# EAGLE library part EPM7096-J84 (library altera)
EPM7096 MAX 7000 family
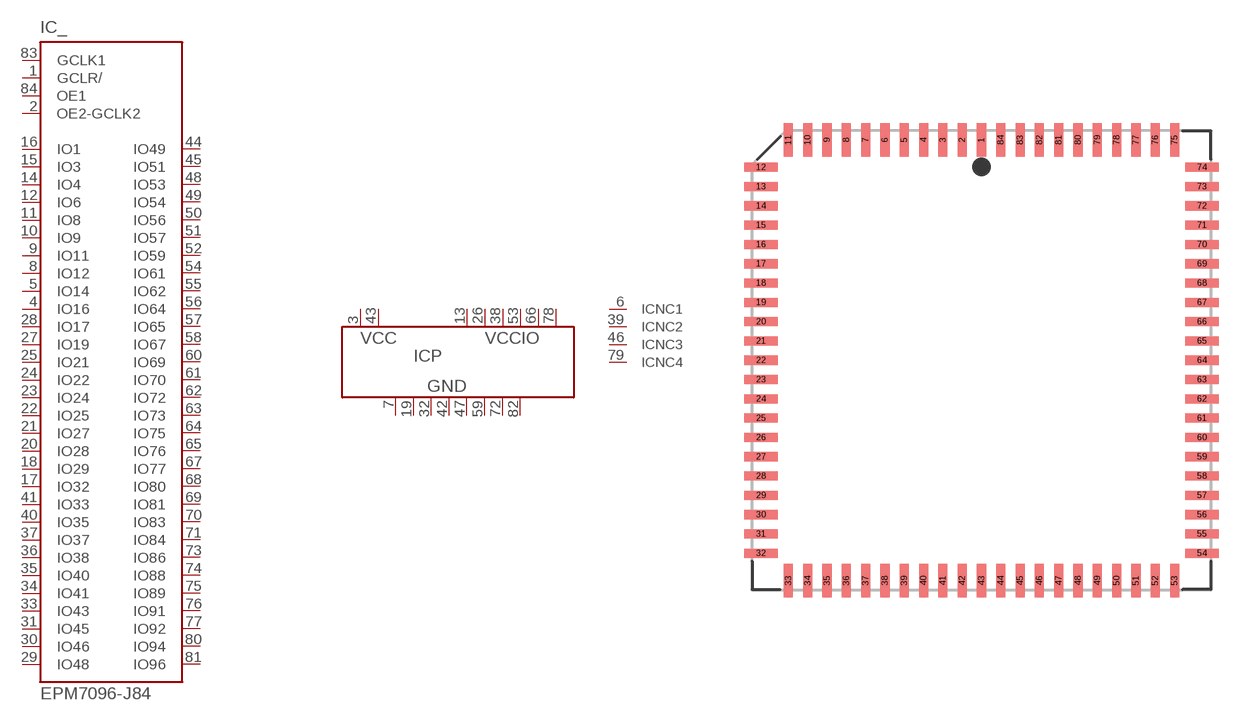
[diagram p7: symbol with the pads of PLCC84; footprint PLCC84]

Designator prefix IC; gates _=7096-84 P=PWR8-2-6 NC1=NC NC2=NC NC3=NC NC4=NC

## EPM7096-J84 (MPN: EPM7096LC84-10; OC_FARNELL: unknown; OC_NEWARK: 51R9659)  [PLCC84]
1  _:GCLR/  in
2  _:OE2-GCLK2  in
3  P:VCC  pwr
4  _:IO16
5  _:IO14
6  NC1:NC  nc
7  P:GND  pwr
8  _:IO12
9  _:IO11
10  _:IO9
11  _:IO8
12  _:IO6
13  P:VCCIO  pwr
14  _:IO4
15  _:IO3
16  _:IO1
17  _:IO32
18  _:IO29
19  P:GND  pwr
20  _:IO28
21  _:IO27
22  _:IO25
23  _:IO24
24  _:IO22
25  _:IO21
26  P:VCCIO  pwr
27  _:IO19
28  _:IO17
29  _:IO48
30  _:IO46
31  _:IO45
32  P:GND  pwr
33  _:IO43
34  _:IO41
35  _:IO40
36  _:IO38
37  _:IO37
38  P:VCCIO  pwr
39  NC2:NC  nc
40  _:IO35
41  _:IO33
42  P:GND  pwr
43  P:VCC  pwr
44  _:IO49
45  _:IO51
46  NC3:NC  nc
47  P:GND  pwr
48  _:IO53
49  _:IO54
50  _:IO56
51  _:IO57
52  _:IO59
53  P:VCCIO  pwr
54  _:IO61
55  _:IO62
56  _:IO64
57  _:IO65
58  _:IO67
59  P:GND  pwr
60  _:IO69
61  _:IO70
62  _:IO72
63  _:IO73
64  _:IO75
65  _:IO76
66  P:VCCIO  pwr
67  _:IO77
68  _:IO80
69  _:IO81
70  _:IO83
71  _:IO84
72  P:GND  pwr
73  _:IO86
74  _:IO88
75  _:IO89
76  _:IO91
77  _:IO92
78  P:VCCIO  pwr
79  NC4:NC  nc
80  _:IO94
81  _:IO96
82  P:GND  pwr
83  _:GCLK1  in
84  _:OE1  in

## Footprint PLCC84 (pad centres in mm)
Plastic J-Lead Chip Carrier
smd 0.6 x 2.2: 1 0,14.5; 2 -1.27,14.5; 3 -2.54,14.5; 4 -3.81,14.5; 5 -5.08,14.5; 6 -6.35,14.5; 7 -7.62,14.5; 8 -8.89,14.5; 9 -10.16,14.5; 10 -11.43,14.5; 11 -12.7,14.5; 33 -12.7,-14.5; 34 -11.43,-14.5; 35 -10.16,-14.5; 36 -8.89,-14.5; 37 -7.62,-14.5; 38 -6.35,-14.5; 39 -5.08,-14.5; 40 -3.81,-14.5; 41 -2.54,-14.5; 42 -1.27,-14.5; 43 0,-14.5; 44 1.27,-14.5; 45 2.54,-14.5; 46 3.81,-14.5; 47 5.08,-14.5; 48 6.35,-14.5; 49 7.62,-14.5; 50 8.89,-14.5; 51 10.16,-14.5; 52 11.43,-14.5; 53 12.7,-14.5; 75 12.7,14.5; 76 11.43,14.5; 77 10.16,14.5; 78 8.89,14.5; 79 7.62,14.5; 80 6.35,14.5; 81 5.08,14.5; 82 3.81,14.5; 83 2.54,14.5; 84 1.27,14.5
smd 2.2 x 0.6: 12 -14.5,12.7; 13 -14.5,11.43; 14 -14.5,10.16; 15 -14.5,8.89; 16 -14.5,7.62; 17 -14.5,6.35; 18 -14.5,5.08; 19 -14.5,3.81; 20 -14.5,2.54; 21 -14.5,1.27; 22 -14.5,0; 23 -14.5,-1.27; 24 -14.5,-2.54; 25 -14.5,-3.81; 26 -14.5,-5.08; 27 -14.5,-6.35; 28 -14.5,-7.62; 29 -14.5,-8.89; 30 -14.5,-10.16; 31 -14.5,-11.43; 32 -14.5,-12.7; 54 14.5,-12.7; 55 14.5,-11.43; 56 14.5,-10.16; 57 14.5,-8.89; 58 14.5,-7.62; 59 14.5,-6.35; 60 14.5,-5.08; 61 14.5,-3.81; 62 14.5,-2.54; 63 14.5,-1.27; 64 14.5,0; 65 14.5,1.27; 66 14.5,2.54; 67 14.5,3.81; 68 14.5,5.08; 69 14.5,6.35; 70 14.5,7.62; 71 14.5,8.89; 72 14.5,10.16; 73 14.5,11.43; 74 14.5,12.7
